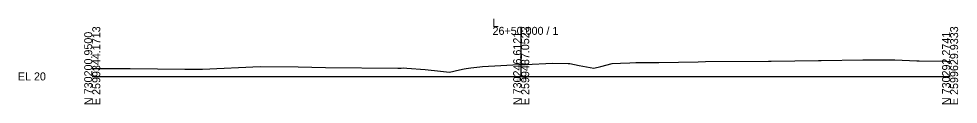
# Model space of a CAD drawing. Extents: x -26 to 3303, y -10 to 9555.
# Drawn here: x 2974.3 to 3302.8, y 2990.3 to 3020.1 of the extents above; entities that cross this region are included whole.
import ezdxf

# ---------------------------------------------------------------- set-up
doc = ezdxf.new("R2010")
doc.units = 0
for name, color, linetype in [('Exist Cross Section Cell', 7, 'Continuous'), ('Exist XS Center Line Elevation Label', 7, 'Continuous'), ('Exist XS Ground Line', 7, 'Continuous')]:
    doc.layers.add(name, color=color, linetype=linetype)

msp = doc.modelspace()

# ---------------------------------------------------------------- linework, layer by layer
at = {"layer": 'Exist Cross Section Cell'}
for p, q in [((3150, 3000), (3150, 3017.31)), ((3000, 3000), (3150, 3000)), ((3150, 3000), (3300, 3000))]:
    msp.add_line(p, q, dxfattribs=at)
at = {"layer": 'Exist XS Ground Line'}
msp.add_lwpolyline([(3000, 3002.76), (3004.14, 3002.8), (3013.23, 3002.82), (3032.41, 3002.48), (3038.53, 3002.53), (3058.74, 3003.44), (3072.03, 3003.39), (3081.58, 3003.17), (3106.9, 3002.92), (3108.01, 3002.92), (3108.97, 3002.94), (3109.99, 3002.84), (3116.44, 3002.39), (3121.83, 3001.81), (3124.89, 3001.46), (3128.38, 3002.25), (3130.07, 3002.67), (3130.76, 3002.74), (3132.37, 3002.94), (3135.55, 3003.33), (3136.5, 3003.44), (3142.93, 3003.8), (3149.18, 3004.14), (3150, 3004.17), (3151.48, 3004.22), (3160.99, 3004.6), (3166.44, 3004.49), (3167, 3004.48), (3170.3, 3003.84), (3175.41, 3002.88), (3177.82, 3003.46), (3181.8, 3004.5), (3184.77, 3004.67), (3188.05, 3004.74), (3190.12, 3004.82), (3195.42, 3004.89), (3198.09, 3004.86), (3211.93, 3005.13), (3214.43, 3005.17), (3236.44, 3005.38), (3237.42, 3005.36), (3254, 3005.54), (3254.91, 3005.55), (3269.52, 3005.75), (3280.66, 3005.77), (3288.4, 3005.49), (3289.22, 3005.49), (3298.51, 3005.27), (3299.26, 3005.24), (3300, 3005.21)], dxfattribs=at)

# ---------------------------------------------------------------- texts
at = {"layer": 'Exist Cross Section Cell'}
for s, p in [('L', (3140, 3017.31)), ('26+50.000 / 1', (3140, 3014.51)), ('EL 20', (2974, 2998.6))]:
    msp.add_text(s, height=2.8, dxfattribs=at).set_placement(p)
for s, p in [('E 2599344.1713', (3002.8, 2990)), ('E 2599487.0523', (3152.8, 2990)), ('E 2599629.9333', (3302.8, 2990)), ('N 730200.9500', (3000, 2990)), ('N 730246.6121', (3150, 2990)), ('N 730292.2741', (3300, 2990))]:
    msp.add_text(s, height=2.8, rotation=90, dxfattribs=at).set_placement(p)
at = {"layer": 'Exist XS Center Line Elevation Label'}
msp.add_text('24.17', height=1, dxfattribs=at).set_placement((3148.37, 2998.67))

doc.saveas('drawing.dxf')
